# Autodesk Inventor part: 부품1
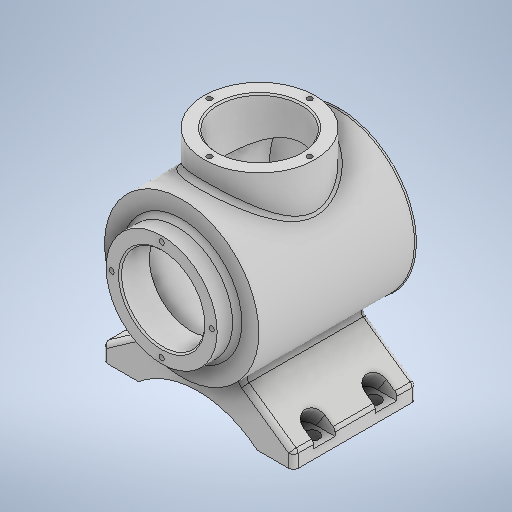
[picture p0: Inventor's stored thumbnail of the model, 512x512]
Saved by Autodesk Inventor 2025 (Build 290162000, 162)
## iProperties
Created: 2024-07
Part Number: 부품1
Material: 일반
Document SubType Name: Modeling
Designer: 학생
Density: 1 g/cm^3
Appearance: 기본값
Author: 학생
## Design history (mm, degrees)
sketch "스케치2"
  geometry: C1 r 50 at (0, 0); 1 further point
  constraints: 1 centre point, 1 coincident
  dimensions: "d10" = 100 diameter of C1
extrude "돌출1" new body sketch "스케치2" stored distance "d11" = 101; taper "d12" = 0 deg
sketch "스케치3"
  geometry: C1 r 36 at (0, 0); 1 further point
  constraints: 1 centre point, 1 coincident
  dimensions: "d13" = 72 diameter of C1
extrude "돌출2" join sketch "스케치3" distance "d14" = 13; taper "d15" = 0 deg
sketch "스케치4"
  geometry: L1 (-112.239, 0)-(112.239, 0); L2 (0, 77)-(0, -77); L3 (-38.5, -77)-(38.5, -77); L4 (38.5, -77)-(62, -77); L5 (62, -77)-(62, -67); L6 (62, -67)-(23.542, -40.072); L7 (-62, -67)-(-23.542, -40.072); L8 (-62, -77)-(-62, -67); L9 (-38.5, -77)-(-62, -77); L10 (-23.542, -40.072)-(23.542, -40.072); A1 r 59.937 centre (0, -122.937) between (38.5, -77) and (-38.5, -77); 3 further points
  constraints: 20 end point, 4 horizontal, 3 midpoint, 3 point on circle, 3 symmetric about line, 1 centre point, 1 coincident, 1 perpendicular, 1 vertical
  dimensions: "d16" = 77 distance of L2.end point (0, 0); "d17" = 77 distance of L3.start L3.end; "d18" = 23.5 distance of L3.end L4.end; "d19" = 10 distance of L4.end L5.end; "d20" = 55 deg angle of L5 L6; "d21" = 14 distance of L2.end point (0, -63)
extrude "돌출3" join sketch "스케치4" stored distance "d22" = 80; taper "d23" = 0 deg
node "작업 평면1"
sketch "스케치5"
  geometry: C1 r 36 at (0, 0); 1 further point
  constraints: 1 centre point, 1 coincident
  dimensions: "d25" = 72 diameter of C1
extrude "돌출4" join sketch "스케치5" distance "d26" = 15; taper "d27" = 0 deg
extrude "돌출5" join sketch "스케치5" stored distance "d28" = 15; taper "d29" = 0 deg
sketch "스케치6"
  geometry: L1 (0, 87.322)-(0, -87.322); L2 (-50, -50.5)-(50, -50.5) reference; A1 r 113 centre (9.729, 55.08) between (0, -57.5) and (50, -50.5); 2 further points
  constraints: 2 end point, 2 point on circle, 1 centre point, 1 coincident, 1 midpoint, 1 point on line, 1 vertical
  dimensions: "d30" = 7 distance from line of A1.start L2; "d34" = 113 radius of A1
feature "회전 곡면1" sketch "스케치6" dims angle "d31" = 90 deg
feature "두껍게 하기1" dims "d32" = 1, "d33" = 1
sketch "스케치7"
  geometry: C1 r 36 at (0, 0) reference; 2 further points
  constraints: 1 coincident
hole "구멍1" sketch "스케치7" at (0, 0) diameter "d35" = 54; stored, may be unused: countersink angle "d39" = 90 deg, drill point angle "d41" = 0 deg; dims "d36" = 6, "d37" = 4, "d38" = 2, "d40" = 19
sketch "스케치8"
  geometry: C1 r 27 at (0, 0) reference; 2 further points
  constraints: 1 coincident
hole "구멍2" sketch "스케치8" at (0, 0) diameter "d42" = 86; stored, may be unused: countersink angle "d46" = 90 deg, drill point angle "d48" = 0 deg; dims "d43" = 6, "d44" = 4, "d45" = 2, "d47" = 94
sketch "스케치9"
  geometry: C1 r 36 at (0, 0) reference; 2 further points
  constraints: 1 coincident
hole "구멍3" sketch "스케치9" at (0, 0) diameter "d49" = 54; stored, may be unused: countersink angle "d53" = 90 deg, drill point angle "d55" = 0 deg; dims "d50" = 6, "d51" = 4, "d52" = 2, "d54" = 40
sketch "스케치10"
  geometry: A1 r 32.5 centre (0, 0) between (0, 32.5) and (-32.5, 0); 3 further points
  constraints: 4 point on circle, 1 centre point, 1 coincident
  dimensions: "d56" = 65 diameter of A1
hole "구멍4" sketch "스케치10" at (0, 32.5), (-32.5, 0), (32.5, 0), (0, -32.5) diameter "d57" = 3.45873; stored, may be unused: countersink angle "d61" = 90 deg, drill point angle "d63" = 120 deg; dims "d58" = 8, "d59" = 4, "d60" = 2, "d62" = 10
sketch "스케치11"
  geometry: A1 r 32.5 centre (0, 0) between (-32.5, 0) and (0, -32.5); 3 further points
  constraints: 4 point on circle, 1 centre point, 1 coincident
  dimensions: "d64" = 65 diameter of A1
hole "구멍5" sketch "스케치11" at (-32.5, 0), (0, -32.5), (32.5, 0), (0, 32.5) diameter "d65" = 3.45873; stored, may be unused: countersink angle "d69" = 90 deg, drill point angle "d71" = 120 deg; dims "d66" = 8, "d67" = 4, "d68" = 2, "d70" = 10
fillet "모깎기1" dims "d72" = 3
chamfer "모따기1" distance "d73" = 1; stored, may be unused: second distance "d74" = 2, angle "d75" = 45 deg
fillet "모깎기2" dims "d76" = 3
chamfer "모따기2" distance "d77" = 1; stored, may be unused: second distance "d78" = 2, angle "d79" = 45 deg
sketch "스케치12"
  geometry: L1 (-38.793, 80)-(0, 80) reference; L2 (0, 80)-(0, 0) reference; L3 (-8, 53)-(8.451, 53); L4 (-8, 67)-(8.451, 67); L5 (8.451, 67)-(8.451, 53); A1 r 7 centre (-8, 60) between (-8, 53) and (-8, 67); 1 further point
  constraints: 6 end point, 2 horizontal, 2 point on circle, 1 centre point, 1 perpendicular
  dimensions: "d80" = 14 diameter of A1; "d81" = 20 distance from line of L1 A1.centre; "d82" = 8 distance from line of A1.centre L2
sketch "스케치13"
  geometry: L1 (23.5, -80)-(23.5, 0) reference; L2 (23.5, -80)-(0, -80) reference; C1 r 4.5 at (15.5, -60); 1 further point
  constraints: 1 centre point
  dimensions: "d83" = 9 diameter of C1; "d85" = 20 distance from line of C1.centre L2; "d86" = 8 distance from line of L1 C1.centre
extrude "돌출6" cut sketch "스케치13" distance "d87" = 6; taper "d88" = 0 deg
extrude "돌출7" cut sketch "스케치12" stored distance "d89" = 16; taper "d90" = 0 deg
fillet "모깎기3" dims "d91" = 3
node "솔리드1"
mirror "미러1"
mirror "미러2"
mirror "미러3"
mirror "미러4"
body "Srf1"
feature "A9D066F2-1C7D-4E18-AEED-F7BC21143FA4" dims "d35" = 54, "d36" = 6, "d37" = 4, "d38" = 2, "d39" = 90 deg, "d40" = 19, "d41" = 0
